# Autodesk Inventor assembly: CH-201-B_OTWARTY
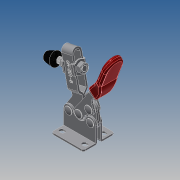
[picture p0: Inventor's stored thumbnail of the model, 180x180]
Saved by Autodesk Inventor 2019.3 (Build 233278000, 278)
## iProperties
Company: Î¢ÈíÖÐ¹ú
Created: 2012-01
Part Number: CH-201-B_OTWARTY
Material: Ogólny
Description: STEP AP203
Document SubType Name: Assembly
Designer: CADENGINEERING4
Sending System: SolidWorks 2010
Preprocessor: SwSTEP 2.0
Title: CH-201-B.STEP
Author: Î¢ÈíÓÃ»§
Revision Number: ÈÎºÎ
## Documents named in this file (9)
- E:\STRONA\Horizontal toggle clamp\CH-201-B\CH-201-B_OTWARTY.iam
- E:\STRONA\Horizontal toggle clamp\CH-201-B\201-B-04.ipt
- E:\STRONA\Horizontal toggle clamp\CH-201-B\201-B-06.ipt
- E:\STRONA\Horizontal toggle clamp\CH-201-B\14134-02.ipt
- E:\STRONA\Horizontal toggle clamp\CH-201-B\201-B-01.ipt
- E:\STRONA\Horizontal toggle clamp\CH-201-B\14134.ipt
- E:\STRONA\Horizontal toggle clamp\CH-201-B\FW140.ipt
- E:\STRONA\Horizontal toggle clamp\CH-201-B\201-B-02.ipt
- E:\STRONA\Horizontal toggle clamp\CH-201-B\201-B.iam
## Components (14 placed, 14 different names)
1. 201-B-04_1 — Zestawiające:14, Zestawiające:15, Zestawiające:16, Zestawiające:22
2. 201-B-06_2 — Zestawiające:10, Zestawiające:11, Zestawiające:27
3. 14134-02_3 — Równoległe:3, Zestawiające:2, Zestawiające:7
4. 201-B-04_4 — Zestawiające:14, Zestawiające:15, Zestawiające:16, Zestawiające:17, Zestawiające:18, Zestawiające:21
5. 201-B-01_5 — Zestawiające:17, Zestawiające:18, Zestawiające:19, Zestawiające:20, Zestawiające:23, Zestawiające:24, Zestawiające:26, Przejściowe:1
6. 14134_6 — Równoległe:3, Zestawiające:1, Zestawiające:2, Zestawiające:3, Zestawiające:4, Zestawiające:9
7. FW140_7 — Równoległe:2, Zestawiające:4, Zestawiające:5, Zestawiające:6
8. 14134-02_8 — Zestawiające:1, Zestawiające:5
9. 201-B-02_9 — Równoległe:1, Zestawiające:6, Zestawiające:8, Zestawiające:9, Zestawiające:25, Zestawiające:26, Zestawiające:27
10. FW140_10 — Równoległe:1, Równoległe:2, Zestawiające:3, Zestawiające:7, Zestawiające:8
11. 201-B_11 [sub-assembly] — Zestawiające:10, Zestawiające:11, Zestawiające:12, Zestawiające:13, Zestawiające:22, Przejściowe:1
12. 201-B-06_12 — Zestawiające:19, Zestawiające:20
13. 201-B-06_13 — Zestawiające:12, Zestawiające:13, Zestawiające:21
14. 201-B-06_14 — Zestawiające:23, Zestawiające:24, Zestawiające:25
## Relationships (31: Mate 27, Flush 3, Transitional 1)
- Równoległe:1 [Flush]: 201-B-02_9 ↔ FW140_10
- Równoległe:2 [Flush]: FW140_7 ↔ FW140_10
- Równoległe:3 [Flush]: 14134-02_3 ↔ 14134_6
- Zestawiające:1 [Mate]: 14134_6 ↔ 14134-02_8
- Zestawiające:2 [Mate]: 14134-02_3 ↔ 14134_6
- Zestawiające:3 [Mate]: 14134_6 ↔ FW140_10
- Zestawiające:4 [Mate]: 14134_6 ↔ FW140_7
- Zestawiające:5 [Mate]: FW140_7 ↔ 14134-02_8
- Zestawiające:6 [Mate]: FW140_7 ↔ 201-B-02_9
- Zestawiające:7 [Mate]: 14134-02_3 ↔ FW140_10
- Zestawiające:8 [Mate]: 201-B-02_9 ↔ FW140_10
- Zestawiające:9 [Mate]: 14134_6 ↔ 201-B-02_9
- Zestawiające:10 [Mate]: 201-B-06_2 ↔ 201-B_11
- Zestawiające:11 [Mate]: 201-B-06_2 ↔ 201-B_11
- Zestawiające:12 [Mate]: 201-B_11 ↔ 201-B-06_13
- Zestawiające:13 [Mate]: 201-B_11 ↔ 201-B-06_13
- Zestawiające:14 [Mate]: 201-B-04_1 ↔ 201-B-04_4
- Zestawiające:15 [Mate]: 201-B-04_1 ↔ 201-B-04_4
- Zestawiające:16 [Mate]: 201-B-04_1 ↔ 201-B-04_4
- Zestawiające:17 [Mate]: 201-B-04_4 ↔ 201-B-01_5
- Zestawiające:18 [Mate]: 201-B-04_4 ↔ 201-B-01_5
- Zestawiające:19 [Mate]: 201-B-01_5 ↔ 201-B-06_12
- Zestawiające:20 [Mate]: 201-B-01_5 ↔ 201-B-06_12
- Zestawiające:21 [Mate]: 201-B-04_4 ↔ 201-B-06_13
- Zestawiające:22 [Mate]: 201-B-04_1 ↔ 201-B_11
- Zestawiające:23 [Mate]: 201-B-01_5 ↔ 201-B-06_14
- Zestawiające:24 [Mate]: 201-B-01_5 ↔ 201-B-06_14
- Zestawiające:25 [Mate]: 201-B-02_9 ↔ 201-B-06_14
- Zestawiające:26 [Mate]: 201-B-01_5 ↔ 201-B-02_9
- Zestawiające:27 [Mate]: 201-B-06_2 ↔ 201-B-02_9
- Przejściowe:1 [Transitional]: 201-B-01_5 ↔ 201-B_11
